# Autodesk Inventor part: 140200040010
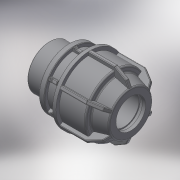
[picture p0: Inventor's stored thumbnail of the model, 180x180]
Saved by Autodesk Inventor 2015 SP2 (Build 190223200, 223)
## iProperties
Created: 2017-08
Part Number: 140200040010
Material: Generic
Description: PLASSON L.14 MALE ADAPTOR (SILVER) 40-1''
Document SubType Name: Modeling
Designer: KIM
Density: 1 g/cm^3
Appearance: Default
Author: KIM
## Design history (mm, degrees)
derived "140200.ipt"
feature "Solid1::140200.ipt"
tag "TaggingFeature1"
body "Solid1"
other parameters: "d2" = 73, "d4" = 15 deg, "d5" = 48.18, "d6" = 15.8994, "d10" = 73, "d16" = 40.8, "d17" = 3.65, "d18" = 97, "d19" = 6.6, "d21" = 6.6, "d22" = 44.88615, "d24" = 3.65, "d25" = 65.7, "d26" = 54.75, "d27" = 3.65, "d28" = 135 deg, "d29" = 2.19, "d31" = 2, "d44" = 0.8, "d45" = 1.2, "d46" = 150 deg, "d49" = 3.65, "d50" = 0, "d51" = 0.73, "d52" = 1.46, "d53" = 45 deg, "d54" = 21, "d55" = 8.4, "d56" = 3.65, "d57" = 0, "d58" = 1.2, "d59" = 0.8, "d61" = 360 deg, "d63" = 33.249, "d64" = 24, "d65" = 22, "d66" = 49.8735, "R_" = 33.249, "E_" = 73, "H_" = 97, "l_" = 73, "l_2" = 22
